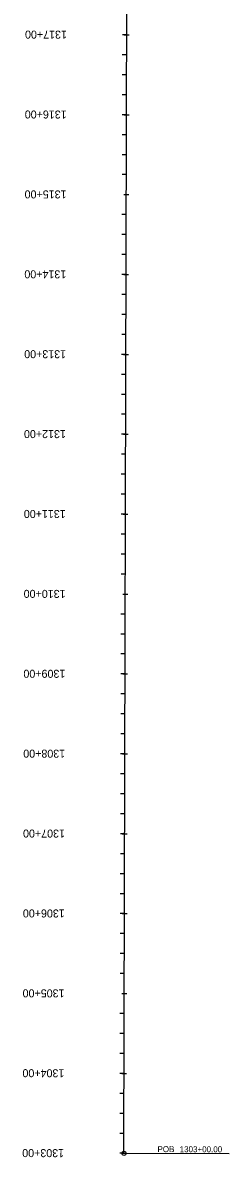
# Model space of a CAD drawing. Extents: x 14541681 to 14544384, y 8572153 to 8583558.
# Drawn here: x 14544125 to 14544384, y 8572153 to 8573573 of the extents above; entities that cross this region are included whole.
import ezdxf

# ---------------------------------------------------------------- set-up
doc = ezdxf.new("R2010")
doc.units = 0
for name, color, linetype in [('Alignment', 7, 'Continuous'), ('TextAlignment', 7, 'Continuous'), ('TextAlignmentLrg', 7, 'Continuous'), ('TextAlignmentSml', 7, 'Continuous')]:
    doc.layers.add(name, color=color, linetype=linetype)

msp = doc.modelspace()

# ---------------------------------------------------------------- linework, layer by layer
at = {"layer": 'Alignment'}
msp.add_line((14544251.8, 8572158.2), (14544263.9, 8577116.3), dxfattribs=at)
at = {"layer": 'TextAlignment'}
for p in [(14544251.8, 8572158.2), (14544383.8, 8572157.8)]:
    msp.add_line(p, (14544383.8, 8572157.8), dxfattribs=at)
msp.add_circle((14544251.8, 8572158.2), 2.67, dxfattribs=at)
at = {"layer": 'TextAlignmentLrg'}
for p, q in [((14544255.2, 8573558.2), (14544249.8, 8573558.2)), ((14544255, 8573458.2), (14544249.5, 8573458.2)), ((14544251.7, 8573358.2), (14544257.8, 8573358.2)), ((14544254.5, 8573258.2), (14544249.1, 8573258.2)), ((14544254.3, 8573158.2), (14544248.8, 8573158.2)), ((14544254, 8573058.2), (14544248.6, 8573058.2)), ((14544253.8, 8572958.2), (14544248.3, 8572958.2)), ((14544250.5, 8572858.2), (14544256.6, 8572858.2)), ((14544253.3, 8572758.2), (14544247.8, 8572758.2)), ((14544253.1, 8572658.2), (14544247.6, 8572658.2)), ((14544252.8, 8572558.2), (14544247.3, 8572558.2)), ((14544252.6, 8572458.2), (14544247.1, 8572458.2)), ((14544249.3, 8572358.2), (14544255.4, 8572358.2)), ((14544252.1, 8572258.2), (14544246.6, 8572258.2)), ((14544251.8, 8572158.2), (14544246.4, 8572158.2))]:
    msp.add_line(p, q, dxfattribs=at)
at = {"layer": 'TextAlignmentSml'}
for p, q in [((14544252.2, 8573558.2), (14544258.3, 8573558.2)), ((14544255.2, 8573533.2), (14544249.7, 8573533.2)), ((14544255.1, 8573508.2), (14544249.7, 8573508.2)), ((14544255.1, 8573483.2), (14544249.6, 8573483.2)), ((14544251.9, 8573458.2), (14544258.1, 8573458.2)), ((14544254.9, 8573433.2), (14544249.5, 8573433.2)), ((14544254.9, 8573408.2), (14544249.4, 8573408.2)), ((14544254.8, 8573383.2), (14544249.4, 8573383.2)), ((14544251.7, 8573358.2), (14544257.8, 8573358.2)), ((14544254.7, 8573333.2), (14544249.2, 8573333.2)), ((14544254.6, 8573308.2), (14544249.2, 8573308.2)), ((14544254.6, 8573283.2), (14544249.1, 8573283.2)), ((14544251.5, 8573258.2), (14544257.6, 8573258.2)), ((14544254.5, 8573233.2), (14544249, 8573233.2)), ((14544254.4, 8573208.2), (14544248.9, 8573208.2)), ((14544254.3, 8573183.2), (14544248.9, 8573183.2)), ((14544251.2, 8573158.2), (14544257.3, 8573158.2)), ((14544254.2, 8573133.2), (14544248.8, 8573133.2)), ((14544254.1, 8573108.2), (14544248.7, 8573108.2)), ((14544254.1, 8573083.2), (14544248.6, 8573083.2)), ((14544251, 8573058.2), (14544257.1, 8573058.2)), ((14544254, 8573033.2), (14544248.5, 8573033.2)), ((14544253.9, 8573008.2), (14544248.4, 8573008.2)), ((14544253.8, 8572983.2), (14544248.4, 8572983.2)), ((14544250.7, 8572958.2), (14544256.8, 8572958.2)), ((14544253.7, 8572933.2), (14544248.3, 8572933.2)), ((14544253.7, 8572908.2), (14544248.2, 8572908.2)), ((14544253.6, 8572883.2), (14544248.1, 8572883.2)), ((14544250.5, 8572858.2), (14544256.6, 8572858.2)), ((14544253.5, 8572833.2), (14544248, 8572833.2)), ((14544253.4, 8572808.2), (14544248, 8572808.2)), ((14544253.4, 8572783.2), (14544247.9, 8572783.2)), ((14544250.2, 8572758.2), (14544256.4, 8572758.2)), ((14544253.2, 8572733.2), (14544247.8, 8572733.2)), ((14544253.2, 8572708.2), (14544247.7, 8572708.2)), ((14544253.1, 8572683.2), (14544247.7, 8572683.2)), ((14544250, 8572658.2), (14544256.1, 8572658.2)), ((14544253, 8572633.2), (14544247.5, 8572633.2)), ((14544252.9, 8572608.2), (14544247.5, 8572608.2)), ((14544252.9, 8572583.2), (14544247.4, 8572583.2)), ((14544249.7, 8572558.2), (14544255.9, 8572558.2)), ((14544252.7, 8572533.2), (14544247.3, 8572533.2)), ((14544252.7, 8572508.2), (14544247.2, 8572508.2)), ((14544252.6, 8572483.2), (14544247.2, 8572483.2)), ((14544249.5, 8572458.2), (14544255.6, 8572458.2)), ((14544252.5, 8572433.2), (14544247, 8572433.2)), ((14544252.4, 8572408.2), (14544247, 8572408.2)), ((14544252.4, 8572383.2), (14544246.9, 8572383.2)), ((14544249.3, 8572358.2), (14544255.4, 8572358.2)), ((14544252.3, 8572333.2), (14544246.8, 8572333.2)), ((14544252.2, 8572308.2), (14544246.7, 8572308.2)), ((14544252.1, 8572283.2), (14544246.7, 8572283.2)), ((14544249, 8572258.2), (14544255.1, 8572258.2)), ((14544252, 8572233.2), (14544246.6, 8572233.2)), ((14544252, 8572208.2), (14544246.5, 8572208.2)), ((14544251.9, 8572183.2), (14544246.4, 8572183.2)), ((14544248.8, 8572158.2), (14544254.9, 8572158.2))]:
    msp.add_line(p, q, dxfattribs=at)

# ---------------------------------------------------------------- texts
at = {"layer": 'TextAlignment'}
for s, p in [('POB ', (14544293.8, 8572159.7)), ('1303+00.00', (14544321.6, 8572159.6))]:
    msp.add_text(s, height=7.5, rotation=359.8604, dxfattribs=at).set_placement(p)
at = {"layer": 'TextAlignmentLrg'}
for s, p in [('1315+00', (14544179.8, 8573363.4)), ('1310+00', (14544178.6, 8572863.4)), ('1305+00', (14544177.3, 8572363.4))]:
    msp.add_text(s, height=10.02, rotation=179.8604, dxfattribs=at).set_placement(p)
at = {"layer": 'TextAlignmentSml'}
for s, p in [('1317+00', (14544180.3, 8573563.4)), ('1316+00', (14544180, 8573463.4)), ('1315+00', (14544179.8, 8573363.4)), ('1314+00', (14544179.5, 8573263.4)), ('1313+00', (14544179.3, 8573163.4)), ('1312+00', (14544179, 8573063.4)), ('1311+00', (14544178.8, 8572963.4)), ('1310+00', (14544178.6, 8572863.4)), ('1309+00', (14544178.3, 8572763.4)), ('1308+00', (14544178.1, 8572663.4)), ('1307+00', (14544177.8, 8572563.4)), ('1306+00', (14544177.6, 8572463.4)), ('1305+00', (14544177.3, 8572363.4)), ('1304+00', (14544177.1, 8572263.4)), ('1303+00', (14544176.8, 8572163.4))]:
    msp.add_text(s, height=10.02, rotation=179.8604, dxfattribs=at).set_placement(p)

doc.saveas('drawing.dxf')
